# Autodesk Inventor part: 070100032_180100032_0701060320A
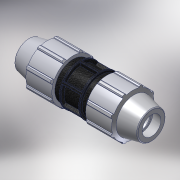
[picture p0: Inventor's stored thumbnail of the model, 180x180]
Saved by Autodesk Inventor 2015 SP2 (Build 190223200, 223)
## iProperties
Created: 2017-02
Part Number: 070100032_180100032_0701060320A
Material: PVC-Piping
Description: PLASSON COUPLER 32-32
Document SubType Name: Modeling
Designer: KIM
Mass: 92.6774 g
Surface Area: 199.44 cm^2
Volume: 66.1981 cm^3
Density: 1.4 g/cm^3
Appearance: PTFE
Author: KIM
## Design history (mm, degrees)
derived "07010.ipt"
feature "Solid1::07010.ipt"
tag "TaggingFeature1"
body "Solid1"
other parameters: "d1" = 145, "d2" = 32, "d4" = 12.08333, "d5" = 20.71429, "d7" = 64, "d8" = 48, "d9" = 20.71429, "d11" = 2.07143, "d12" = 51.2, "d13" = 120 deg, "d14" = 48, "d15" = 10 deg, "d16" = 57.6, "d18" = 1.6, "d19" = 35 deg, "d20" = 17.5 deg, "d21" = 59.52, "d23" = 0, "d25" = 360 deg, "d27" = 1.28, "d33" = 0.64, "d34" = 3.2, "d36" = 0, "d37" = 0.64, "d38" = 0.64, "d40" = 360 deg, "d42" = 31.9, "d43" = 1.92, "d46" = 0.96, "d49" = 71, "d50" = 25.6, "d_" = 32, "E_" = 64, "H_" = 145, "l_" = 71
